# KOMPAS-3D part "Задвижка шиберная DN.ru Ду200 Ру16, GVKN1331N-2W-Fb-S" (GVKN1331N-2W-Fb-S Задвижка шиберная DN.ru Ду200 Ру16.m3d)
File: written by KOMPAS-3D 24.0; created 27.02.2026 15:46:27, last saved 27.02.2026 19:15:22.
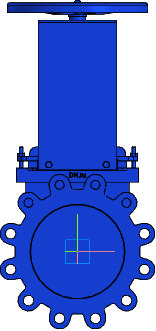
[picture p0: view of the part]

Document properties: Автор: R2D2; Полное имя файла: GVKN1331N-2W-Fb-S Задвижка шиберная DN.ru Ду200 Ру16.cdw

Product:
- Part/product: Задвижка шиберная DN.ru Ду200 Ру16  | designation GVKN1331N-2W-Fb-S
    Масса: 26.5
    Раздел спецификации: Прочие изделия
    Форматы листов документа: A2
    Примечание: D040-09387
    additional columns: D040-09387

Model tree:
1. Операция без истории:3

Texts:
  GVKN1331N-2W-Fb-S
